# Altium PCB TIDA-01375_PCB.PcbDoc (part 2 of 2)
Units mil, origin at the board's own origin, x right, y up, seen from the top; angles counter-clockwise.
Board outline 3937.01 x 3149.61 mil, 2 copper layers (Top Layer, Bottom Layer), stack 62 mil thick; 52 components, 33 nets, 136 pads, 897 vias.
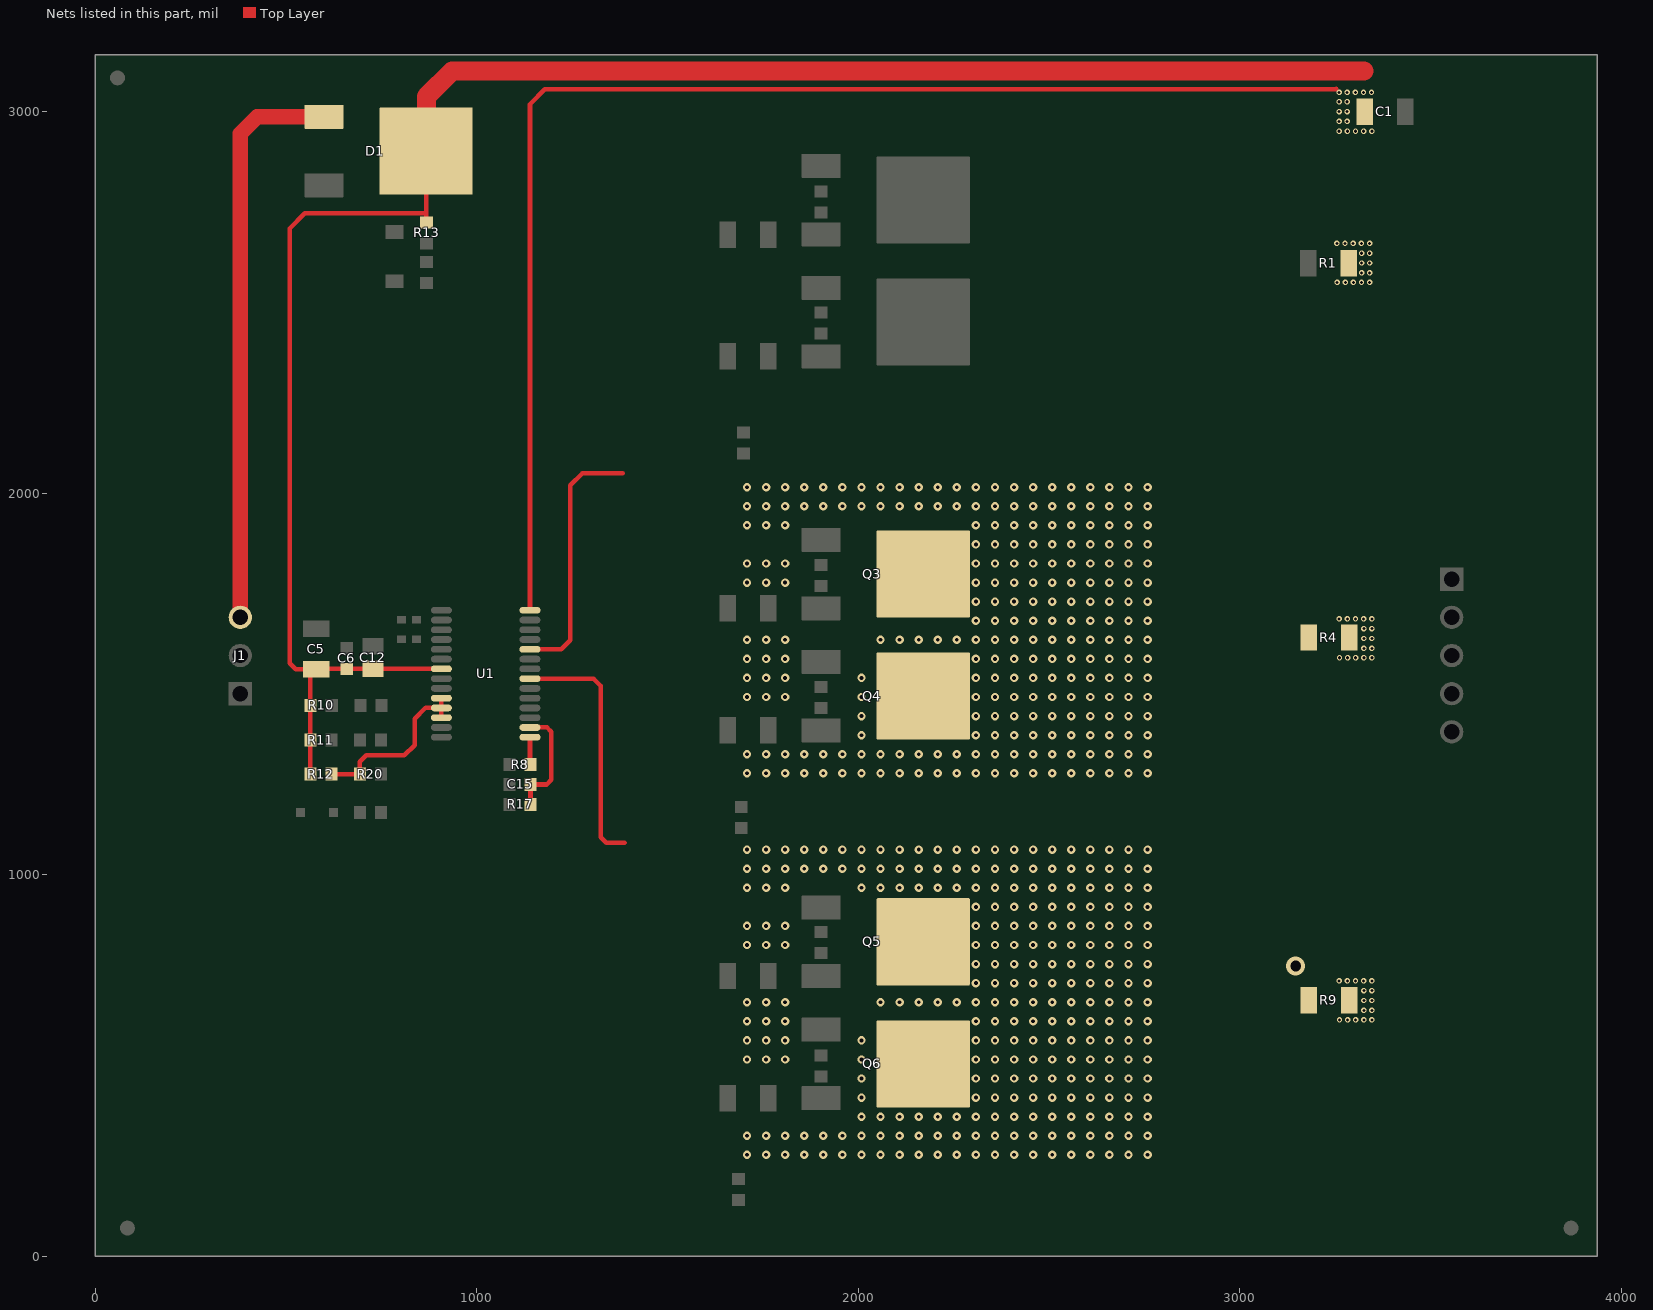
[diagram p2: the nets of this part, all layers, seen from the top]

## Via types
v1: diameter 22, hole 10, Top Layer to Bottom Layer, 824 vias
v2: diameter 14, hole 8, Top Layer to Bottom Layer, 64 vias
v3: diameter 30, hole 18, Top Layer to Bottom Layer, 8 vias
v4: diameter 50, hole 28, Top Layer to Bottom Layer, 1 vias

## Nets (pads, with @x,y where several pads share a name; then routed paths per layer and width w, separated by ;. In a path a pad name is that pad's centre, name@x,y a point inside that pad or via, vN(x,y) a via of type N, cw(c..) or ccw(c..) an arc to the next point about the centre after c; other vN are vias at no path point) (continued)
NetQ3_4: Q3.4 Q4.4 R4.1 U1.24 | length 671.6
  Top Layer w12: U1.24@1139.14,1590.98 1220.98,1590.98 1244.75,1614.75 1244.75,2020.75 1276,2052 1382,2052
  other v1: 1708,1266 1758,1266 1808,1266 1858,1266 1908,1266 1958,1266 2008,1266 2058,1266 2108,1266 2158,1266 2208,1266 2258,1266 2308,1266 2358,1266 2408,1266 2458,1266 2508,1266 2558,1266 2608,1266 2658,1266 2708,1266 2758,1266 1708,1316 1758,1316 1808,1316 1858,1316 1908,1316 1958,1316 2008,1316 2058,1316 2108,1316 2158,1316 2208,1316 2258,1316 2308,1316 2358,1316 2408,1316 2458,1316 2508,1316 2558,1316 2608,1316 2658,1316 2708,1316 2758,1316 2008,1366 2308,1366 2358,1366 2408,1366 2458,1366 2508,1366 2558,1366 2608,1366 2658,1366 2708,1366 2758,1366 2008,1416 2308,1416 2358,1416 2408,1416 2458,1416 2508,1416 2558,1416 2608,1416 2658,1416 2708,1416 2758,1416 1708,1466 1758,1466 1808,1466 2008,1466 2308,1466 2358,1466 2408,1466 2458,1466 2508,1466 2558,1466 2608,1466 2658,1466 2708,1466 2758,1466 1708,1516 1758,1516 1808,1516 2008,1516 2308,1516 2358,1516 2408,1516 2458,1516 2508,1516 2558,1516 2608,1516 2658,1516 2708,1516 2758,1516 1708,1566 1758,1566 1808,1566 2308,1566 2358,1566 2408,1566 2458,1566 2508,1566 2558,1566 2608,1566 2658,1566 2708,1566 2758,1566 1708,1616 1758,1616 1808,1616 2058,1616 2108,1616 2158,1616 2208,1616 2258,1616 2308,1616 2358,1616 2408,1616 2458,1616 2508,1616 2558,1616 2608,1616 2658,1616 2708,1616 2758,1616 2308,1666 2358,1666 2408,1666 2458,1666 2508,1666 2558,1666 2608,1666 2658,1666 2708,1666 2758,1666 2308,1716 2358,1716 2408,1716 2458,1716 2508,1716 2558,1716 2608,1716 2658,1716 2708,1716 2758,1716 1708,1766 1758,1766 1808,1766 2308,1766 2358,1766 2408,1766 2458,1766 2508,1766 2558,1766 2608,1766 2658,1766 2708,1766 2758,1766 1708,1816 1758,1816 1808,1816 2308,1816 2358,1816 2408,1816 2458,1816 2508,1816 2558,1816 2608,1816 2658,1816 2708,1816 2758,1816 2308,1866 2358,1866 2408,1866 2458,1866 2508,1866 2558,1866 2608,1866 2658,1866 2708,1866 2758,1866 1708,1916 1758,1916 1808,1916 2308,1916 2358,1916 2408,1916 2458,1916 2508,1916 2558,1916 2608,1916 2658,1916 2708,1916 2758,1916 1708,1966 1758,1966 1808,1966 1858,1966 1908,1966 1958,1966 2008,1966 2058,1966 2108,1966 2158,1966 2208,1966 2258,1966 2308,1966 2358,1966 2408,1966 2458,1966 2508,1966 2558,1966 2608,1966 2658,1966 2708,1966 2758,1966 1708,2016 1758,2016 1808,2016 1858,2016 1908,2016 1958,2016 2008,2016 2058,2016 2108,2016 2158,2016 2208,2016 2258,2016 2308,2016 2358,2016 2408,2016 2458,2016 2508,2016 2558,2016 2608,2016 2658,2016 2708,2016 2758,2016
NetQ5_4: Q5.4 Q6.4 R9.1 U1.21 | length 658.6
  Top Layer w12: U1.21@1139.14,1514.2 1305.8,1514.2 1325,1495 1325,1098 1339,1084 1387,1084
  other v1: 1708,266 1758,266 1808,266 1858,266 1908,266 1958,266 2008,266 2058,266 2108,266 2158,266 2208,266 2258,266 2308,266 2358,266 2408,266 2458,266 2508,266 2558,266 2608,266 2658,266 2708,266 2758,266 1708,316 1758,316 1808,316 1858,316 1908,316 1958,316 2008,316 2058,316 2108,316 2158,316 2208,316 2258,316 2308,316 2358,316 2408,316 2458,316 2508,316 2558,316 2608,316 2658,316 2708,316 2758,316 2008,366 2058,366 2108,366 2158,366 2208,366 2258,366 2308,366 2358,366 2408,366 2458,366 2508,366 2558,366 2608,366 2658,366 2708,366 2758,366 2008,416 2308,416 2358,416 2408,416 2458,416 2508,416 2558,416 2608,416 2658,416 2708,416 2758,416 2008,466 2308,466 2358,466 2408,466 2458,466 2508,466 2558,466 2608,466 2658,466 2708,466 2758,466 1708,516 1758,516 1808,516 2008,516 2308,516 2358,516 2408,516 2458,516 2508,516 2558,516 2608,516 2658,516 2708,516 2758,516 1708,566 1758,566 1808,566 2008,566 2308,566 2358,566 2408,566 2458,566 2508,566 2558,566 2608,566 2658,566 2708,566 2758,566 1708,616 1758,616 1808,616 2308,616 2358,616 2408,616 2458,616 2508,616 2558,616 2608,616 2658,616 2708,616 2758,616 1708,666 1758,666 1808,666 2058,666 2108,666 2158,666 2208,666 2258,666 2308,666 2358,666 2408,666 2458,666 2508,666 2558,666 2608,666 2658,666 2708,666 2758,666 2308,716 2358,716 2408,716 2458,716 2508,716 2558,716 2608,716 2658,716 2708,716 2758,716 2308,766 2358,766 2408,766 2458,766 2508,766 2558,766 2608,766 2658,766 2708,766 2758,766 1708,816 1758,816 1808,816 2308,816 2358,816 2408,816 2458,816 2508,816 2558,816 2608,816 2658,816 2708,816 2758,816 1708,866 1758,866 1808,866 2308,866 2358,866 2408,866 2458,866 2508,866 2558,866 2608,866 2658,866 2708,866 2758,866 2308,916 2358,916 2408,916 2458,916 2508,916 2558,916 2608,916 2658,916 2708,916 2758,916 1708,966 1758,966 1808,966 2008,966 2058,966 2108,966 2158,966 2208,966 2258,966 2308,966 2358,966 2408,966 2458,966 2508,966 2558,966 2608,966 2658,966 2708,966 2758,966 1708,1016 1758,1016 1808,1016 1858,1016 1908,1016 1958,1016 2008,1016 2058,1016 2108,1016 2158,1016 2208,1016 2258,1016 2308,1016 2358,1016 2408,1016 2458,1016 2508,1016 2558,1016 2608,1016 2658,1016 2708,1016 2758,1016 1708,1066 1758,1066 1808,1066 1858,1066 1908,1066 1958,1066 2008,1066 2058,1066 2108,1066 2158,1066 2208,1066 2258,1066 2308,1066 2358,1066 2408,1066 2458,1066 2508,1066 2558,1066 2608,1066 2658,1066 2708,1066 2758,1066
  other v4: 3146,761
NetR8_2: R8.2 U1.15 | length 72.2
  Top Layer w12: U1.15@1139.14,1360.66 1139.14,1290.42 R8.2@1140.56,1289
PL: D1.1 J1.3 | length 1505.5
  Top Layer w40: J1.3@380,1674.8 380,2943 423.76,2986.76 D1.1@599.14,2986.76
PWMCHG: C15.1 R17.2 U1.16 | length 298.3
  Top Layer w12: U1.16@1139.14,1386.25 1183.75,1386.25 1195,1375 1195,1249 1182.71,1236.71 C15.1@1140.56,1236.71 R17.2@1140.56,1184.43
PWMIN: R12.1 R20.2 U1.10 U1.11 U1.12 | length 470.7
  Top Layer w12: R12.1@618.56,1264 R20.2@693.44,1264 693.44,1296.44 710,1313 810,1313 837,1340 837,1409 865.43,1437.43 U1.11@906.86,1437.43 ; U1.12@906.86,1411.84 U1.11@906.86,1437.43 ; U1.10@906.86,1463.02 U1.11@906.86,1437.43
VIN: C1.1 C5.1 C6.1 C12.2 D1.4 R1.2 R4.2 R9.2 R10.2 R11.2 R12.2 R13.2 U1.7 U1.28 | length 8361.2
  Top Layer w12: R12.2@563.44,1264 R11.2@563.44,1353 563.44,1523.1 C5.1@579,1538.66 ; D1.4@866.86,2897 866.86,2737 ; R13.2@868,2710.09 866.86,2711.23 866.86,2737 ; U1.7@906.86,1539.8 727.34,1539.8 C12.2@727.18,1539.64 579.98,1539.64 C5.1@579,1538.66 ; U1.28@1139.14,1693.34 1139.14,3020.14 1178,3059 3251,3059 3252,3060 ; C5.1@579,1538.66 525.34,1538.66 509,1555 509,2694 549,2734 863.86,2734 866.86,2737
  Top Layer w50: D1.4@868,3008 868,3040 935,3107 3325,3107
  other v2: 3261,620 3282.25,620 3303.5,620 3324.75,620 3346,620 3325,644.75 3346,644.75 3325,670.5 3346,670.5 3325,696.25 3346,696.25 3260,722 3281.5,722 3303,722 3324.5,722 3346,722 3261,1569 3282.25,1569 3303.5,1569 3324.75,1569 3346,1569 3325,1593.75 3346,1593.75 3325,1619.5 3346,1619.5 3325,1645.25 3346,1645.25 3260,1671 3281.5,1671 3303,1671 3324.5,1671 3346,1671 3255,2553 3276.25,2553 3297.5,2553 3318.75,2553 3340,2553 3319,2577.75 3340,2577.75 3319,2603.5 3340,2603.5 3319,2629.25 3340,2629.25 3254,2655 3275.5,2655 3297,2655 3318.5,2655 3340,2655 3260,2949 3281.5,2949 3303,2949 3324.5,2949 3346,2949 3260,2974.75 3281,2974.75 3260,3000.5 3281,3000.5 3260,3026.25 3281,3026.25 3260,3051 3281.25,3051 3302.5,3051 3323.75,3051 3345,3051
pads on no net: FID1.1 FID2.1 FID3.1 U1.18

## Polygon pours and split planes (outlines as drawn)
GND on Top Layer "Top Layer-No Net1" (solid, remove dead copper, pour order 12): 0,0 3937.01,0 3937.01,3149.61 0,3149.61
NetQ1_4 on Top Layer "Top Layer-No Net" (solid, remove dead copper, pour order 4): 1368.8,3037.55 1369.8,3037.55 3203.8,3037.55 3203.8,2186.55 3203.8,2185.55 3202.8,2185.55 1368.8,2186.55
NetQ3_4 on Top Layer "Top Layer-No Net" (solid, remove dead copper, pour order 2): 1368.8,2059 1369.8,2059 3203.8,2059 3203.8,1208 3203.8,1207 3202.8,1207 1368.8,1207
NetQ5_4 on Top Layer "Top Layer-No Net" (solid, remove dead copper, pour order 0): 1368.8,1092.45 1369.8,1092.45 3200,1092.45 3200,240.45 1368.8,241.45
GND on Bottom Layer "Top Layer-No Net2" (solid, remove dead copper, pour order 13): 0,0 3937.01,0 3937.01,3149.61 0,3149.61
NetQ5_4 on Bottom Layer "Top Layer-No Net" (solid, remove dead copper, pour order 10): 1368.8,1092.45 1369.8,1092.45 3200,1092.45 3200,240.45 1368.8,241.45
NetQ3_4 on Bottom Layer "Top Layer-No Net" (solid, remove dead copper, pour order 8): 1368.8,2059 1369.8,2059 3203.8,2059 3203.8,1208 3203.8,1207 3202.8,1207 1368.8,1207
NetQ1_4 on Bottom Layer "Top Layer-No Net" (solid, remove dead copper, pour order 6): 1368.8,3037.55 1369.8,3037.55 3203.8,3037.55 3203.8,2186.55 3203.8,2185.55 3202.8,2185.55 1368.8,2186.55

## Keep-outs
Keep-Out Layer:
  the board outline again, w10
  text ".Layer_Name" at 577,-858.49 h60

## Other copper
Top Layer:
  rectangle net VIN: 3246,599 3358,749
  rectangle net VIN: 3246,1548 3358,1698
  rectangle net VIN: 3244,2535 3358,3132
  text ".Layer_Name" at 577,-858.49 h60
Bottom Layer:
  rectangle net VIN: 3246,599 3358,3131
  text ".Layer_Name" at 577,-858.49 h60

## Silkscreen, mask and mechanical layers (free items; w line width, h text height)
Top Overlay:
  text ".PRJ_Number" at 369,110 h60
  text ".PCB_Rev" at 969,110 h60
  text ".Layer_Name" at 577,-858.49 h60
Bottom Overlay:
  text ".Layer_Name" at 577,-858.49 h60
Top Paste:
  text ".Layer_Name" at 577,-858.49 h60
Bottom Paste:
  text ".Layer_Name" at 577,-858.49 h60
Top Solder:
  text ".Layer_Name" at 577,-858.49 h60
  text ".Layer_Name" at 577,-858.49 h60
Bottom Solder:
  text ".Layer_Name" at 577,-858.49 h60
Drill Guide:
  text ".Layer_Name" at 577,-858.49 h60
M1 Board Outline:
  the board outline again, w10
  text ".Layer_Name" at 577,-858.49 h60
M2 Board Dimensions:
  rectangle: 0,-275 125,-150
  rectangle: 125,-400 500,-275
  lines w7: 0,-275 1000,-275 ; 125,-400 125,-150 ; 250,-400 250,-150 ; 500,-400 500,-150 ; 750,-400 750,-150 ; 0,-400 1000,-400 1000,-150 0,-150 0,-400
  text ".Layer_Name" at 577,-858.49 h60
M3 3D STEP Top:
  text ".Layer_Name" at 577,-858.49 h60
M4 3D STEP Bottom:
  text ".Layer_Name" at 577,-858.49 h60
M5 Assembly Top:
  lines w10: -292,-930.17 6308,-930.17 ; -292,-726.83 6310,-726.83 ; -292,-523.5 -292,-1133.5 3713,-1133.5 6310,-1133.5 6310,-523.5 -291.5,-523.5 -291.5,-1133.5 1284,-1133.5 ; 2173,-1133.5 2173,-523.5 ; 3440,-726.83 3440,-523.5 ; 4280,-726.83 4280,-523.5 ; 4902,-1140 4902,-937.17
  text "COMPONENTS MARKED 'DNP' SHOULD NOT BE POPULATED." at 1153.5,-318.5 h60
  text "ASSEMBLY VARIANT:" at 1153,-434 h60
  text ".VariantName" at 2189,-434 h60
  text "PCB VIEWED FROM TOP SIDE" at -228.5,-655.67 h60
  text "BOARD #:" at 2248,-655.67 h60
  text ".PRJ_Number" at 2793.5,-655.67 h60
  text "REV:" at 3638,-655.67 h60
  text ".PCB_Rev" at 3929.5,-655.67 h60
  text "SVN REV:" at 4476,-655.67 h60
  text ".VersionControl_RevNumber" at 4982,-655.67 h60
  text "TID #:" at 2248,-859 h60
  text ".TID" at 2793.5,-859 h60
  text "PLOT NAME =" at -228.5,-1064.34 h60
  text ".plot_File_Name" at 577,-1064.34 h60
  text "GENERATED    :" at 2250,-1064.34 h60
  text ".Print_Date" at 3119.5,-1064.34 h60
  text ".Print_Time" at 3848.5,-1064.34 h60
  text "TEXAS INSTRUMENTS" at 5113,-1064.34 h60
M6 Assembly Bottom:
  lines w10: -292.5,-727.33 6309.5,-727.33 ; -290.5,-930.67 6309.5,-930.67 ; 1115.5,-1140.5 1115.5,-937.67 ; 1737.5,-727.33 1737.5,-524 ; 2577.5,-727.33 2577.5,-524 ; 3844.5,-1134 3844.5,-524 ; 4733.5,-1134 6309,-1134 6309,-524 -292.5,-524 -292.5,-1134 2304.5,-1134 6309.5,-1134 6309.5,-524
  text "COMPONENTS MARKED 'DNP' SHOULD NOT BE POPULATED." at 6102,-318 h60
  text ".VariantName" at 5058,-434 h60
  text "ASSEMBLY VARIANT:" at 6097,-434 h60
  text ".VersionControl_RevNumber" at 1035.5,-656.17 h60
  text "SVN REV:" at 1541.5,-656.17 h60
  text ".PCB_Rev" at 2088,-656.17 h60
  text "REV:" at 2379.5,-656.17 h60
  text ".PRJ_Number" at 3224,-656.17 h60
  text "BOARD #:" at 3769.5,-656.17 h60
  text "PCB VIEWED FROM BOTTOM SIDE" at 6246,-656.17 h60
  text ".TID" at 3224,-859.5 h60
  text "TID #:" at 3769.5,-859.5 h60
  text "TEXAS INSTRUMENTS" at 904.5,-1064.84 h60
  text ".Print_Time" at 2169,-1064.84 h60
  text ".Print_Date" at 2898,-1064.84 h60
  text "GENERATED    :" at 3767.5,-1064.84 h60
  text ".plot_File_Name" at 5440.5,-1064.84 h60
  text "PLOT NAME =" at 6246,-1064.84 h60
M9 Title Sheet:
  drawing of 57 lines, arcs and shapes, not listed
  text "1" at 739.84,8036.5 h70
  text "2" at 3235.5,8036.5 h70
  text "3" at 5724.84,8036.5 h70
  text "4" at 8231.51,8036.5 h70
  text "5" at 10730.5,8036.5 h70
  text "6" at 13235.5,8036.5 h70
  text "A" at -416.5,6893.5 h70
  text "A" at 14383.5,6893.5 h70
  text "B" at -416.5,4513.5 h70
  text "B" at 14383.5,4513.5 h70
  text "C" at -416.5,2138.5 h70
  text "C" at 14383.5,2138.5 h70
  text "PROJECT TITLE:" at 11343.5,277.5 h45
  text ".PRJ_Title" at 11393.5,144.17 h70
  text "DESIGNED FOR:" at 11343.5,-23.5 h45
  text ".PRJ_Customer" at 11393.5,-163.5 h70
  text "D" at -416.5,-231.5 h70
  text "D" at 14383.5,-231.5 h70
  text "FILE NAME:" at 11343.5,-323.5 h45
  text ".PCB_File_Name_No_Path" at 11393.5,-443.5 h70
  text "Texas Instruments (TI) and/or its licensors do not warrant the accuracy or completeness of this specification" at 6374,-605.34 h45
  text "ENGINEER:" at 11343.5,-613.5 h45
  text "LAYOUT BY:" at 12848.5,-613.5 h45
  text "or any information contained therein. TI and/or its licensors do not warrant that this design will meet" at 6329.01,-718 h45
  text ".PRJ_Engineer" at 11393.5,-768.49 h70
  text ".PCB_Layout" at 12899,-768.49 h70
  text "the specifications, will be suitable for your application or fit for any particular purpose, or will operate in" at 6329.01,-830.67 h45
  text ".Layer_Name" at 577,-858.49 h60
  text "ALTIUM DESIGNER VERSION:" at 12848.5,-923.5 h45
  text "an implementation. TI and/or its licensors do not warrant that the design is production worthy. You should" at 6329.01,-943.33 h45
  text "completely validate and test your design implementation to confirm the system functionality for your application." at 6374,-1056 h45
  text ".print_Scale" at 11393.5,-1056.83 h70
  text ".Application_BuildNumber" at 12899,-1056.83 h70
  text "1" at 739.84,-1263.5 h70
  text "2" at 3235.5,-1263.5 h70
  text "3" at 5724.84,-1263.5 h70
  text "4" at 8231.51,-1263.5 h70
  text "5" at 10730.5,-1263.5 h70
  text "6" at 13235.5,-1263.5 h70
M10 Fab Notes:
  drawing of 173 lines, arcs and shapes, not listed
  text "DESIGN INFORMATION" at 12377.02,6201 h60
  text "MIN. TRACK WIDTH:" at 11732.46,6021 h60
  text "8" at 12828.7,6021 h60
  text "MIL" at 12983.46,6021 h60
  text "MIN. CLEARANCE:" at 11732.46,5889 h60
  text "0.2" at 12768.7,5889 h60
  text "mm" at 12983.46,5889 h60
  text "MIN. VIA PAD SIZE:" at 11732.46,5757 h60
  text "24" at 12798.71,5757 h60
  text "MIL" at 12983.46,5757 h60
  text "0.05mm (2MIL)" at 12427.46,5615.29 h60
  text "MINIMUM ANNULAR RING" at 11403.23,5611 h60
  text "EXTERNAL" at 13135.46,5611 h60
  text "PER" at 11603.23,5493 h60
  text "IPC-D-275 CLASS 2 LEVEL C" at 11823.23,5493 h60
  text "MIL, HOLES" at 13311.46,5380.71 h60
  text "+/-" at 12919,5380 h60
  text "+/-" at 13773,5380 h60
  text "REGISTRATION TOLERANCES:" at 11403.23,5375 h60
  text "METAL" at 12603,5375 h60
  text "5" at 13179.2,5375 h60
  text "3" at 14012.2,5375 h60
  text "MIL" at 14128.46,5375 h60
  text "+/-" at 13773,5262 h60
  text "HOLE SIZE TOLERANCE (UNLESS OTHERWISE SPECIFIED):" at 11403.23,5257 h60
  text "3" at 14012.2,5257 h60
  text "MIL" at 14128.46,5257 h60
  text "MATERIAL:" at 11328.46,5047.54 h60
  text "FR-4 High Tg" at 12314.9,4907.21 h60
  text "FR-408" at 11749.46,4898.64 h60
  text "OTHER" at 13237.46,4898.64 h60
  text "X" at 12160,4895 h60
  text "62 MIL (1.6mm) +/-10%" at 12069.56,4735.92 h60
  text "THICKNESS:" at 11403.23,4731.64 h60
  text "X" at 11941.4,4731.64 h60
  text "OTHER" at 13354.46,4731.64 h60
  text "TOLERANCE:" at 11403.23,4573.64 h60
  text "X" at 12242.53,4573.64 h60
  text "ANSI IPC-6012 TYPE 3 CLASS 2" at 12429.48,4573.64 h60
  text "OTHER +/-" at 12429.46,4417.64 h60
  text "BOW & TWIST:" at 11403.23,4260.64 h60
  text "X" at 12242.53,4260.64 h60
  text "ANSI IPC-6012 TYPE 3 CLASS 2" at 12429.48,4260.64 h60
  text "OTHER +/-" at 12429.46,4102.13 h60
  text "DRILLING:" at 11328.46,3963.64 h60
  text "REFERENCE:" at 11403.23,3846.64 h60
  text "X" at 12051.46,3846.64 h60
  text "AS SHOWN" at 12238.46,3846.64 h60
  text "X" at 12952.46,3846.64 h60
  text "NC_DRILL FILES" at 13089.46,3846.64 h60
  text "PTH COPPER THICKNESS:" at 11403.23,3688.64 h60
  text "X" at 12533.46,3688.64 h60
  text "20-30 um" at 12670.46,3688.64 h60
  text "OTHER" at 13387.46,3688.64 h60
  text "BOARD FINISH:" at 11328.46,3529.64 h60
  text "SILKSCREEN:" at 11483.68,3411.64 h60
  text "X" at 12432.46,3411.64 h60
  text "TOP" at 12558.46,3411.64 h60
  text "X" at 12942.46,3411.64 h60
  text "BOTTOM" at 13069.46,3411.64 h60
  text "SILKSCREEN COLOR:" at 11483.68,3244.64 h60
  text "X" at 12431.42,3244.64 h60
  text "WHITE" at 12558.46,3244.64 h60
  text "OTHER" at 13069.46,3244.64 h60
  text "X" at 12562.42,3085.44 h60
  text "GREEN" at 12689.46,3085.44 h60
  text "OTHER" at 13307.46,3085.44 h60
  text "SOLDER RESIST COLOR:" at 11483.68,3074.64 h60
  text "X" at 12562.42,2915.44 h60
  text "MATTE" at 12689.46,2915.44 h60
  text "SEMI-GLOSS" at 13307,2914.8 h60
  text "IMMERSION GOLD (ENIG)" at 12389.46,2726.92 h60
  text "ENEPIG" at 13727,2723.64 h60
  text "SURFACE FINISH:" at 11328.46,2722.64 h60
  text "X" at 12202.51,2722.64 h60
  text "IMM. TIN/SILVER OR EQUIV" at 11658,2565.64 h60
  text "OTHER" at 13089.46,2565.64 h60
  text "ARRAY/PANEL:" at 11328.46,2386.64 h60
  text "CUT AND TRIM PER M1 BOARD OUTLINE" at 12389.46,2382.35 h60
  text "N.C. ROUTE" at 12389.46,2230.64 h60
  text "X" at 13068.46,2230.64 h60
  text "V. SCORE" at 13255.46,2230.64 h60
  text "CERTIFICATION:" at 11328.46,2093.64 h60
  text "MATERIALS AND WORKMANSHIP FOR ALL PCBS" at 12053.46,2093.64 h60
  text "TO MEET OR EXCEED THE REQUIREMENTS OF:" at 12053.46,1995.64 h60
  text "X" at 11679.96,1859.13 h60
  text "ANSI IPC-A-600F CLASS ->" at 11818.96,1859.13 h60
  text "X" at 13458.02,1859.13 h60
  text "2" at 13576.96,1859.14 h60
  text "1" at 13261.96,1857.64 h60
  text "3" at 13930.96,1857.64 h60
  text "X" at 12494.02,1699.64 h60
  text "RoHS" at 12630.96,1699.64 h60
  text "OTHER" at 13275.36,1699.64 h60
  text "PER ORDER" at 13672.42,1699.64 h60
  text "ALL BOARDS MUST MEET OR EXCEED UL94-V0 REQUIREMENTS." at 11356,1534 h60
  text "PCB MUST BEAR THE UL94V-0 UL REGISTERED MATERIAL ID NUMBER" at 11356,1414 h60
  text "ADDITIONAL REQUIREMENTS:" at 11328.46,1240.64 h60
  text "MICROSECTION:" at 11403.23,1125.64 h60
  text "YES" at 12308.96,1125.64 h60
  text "REQUIRED" at 13170.46,969.49 h60
  text "BARE BOARD ELEC. TEST:" at 11403.23,966.64 h60
  text "NONE" at 12708.96,966.64 h60
  text "X" at 13043.46,966.64 h60
  text "PER ORDER" at 13762.46,966.64 h60
  text ".Layer_Name" at 577,-858.49 h60
M11 Gerber Information:
  lines w10: -292,-930.17 6308,-930.17 ; -292,-726.83 6310,-726.83 ; -292,-523.5 -292,-1133.5 3713,-1133.5 6310,-1133.5 6310,-523.5 -291.5,-523.5 -291.5,-1133.5 1284,-1133.5 ; 2173,-1133.5 2173,-523.5 ; 3440,-726.83 3440,-523.5 ; 4280,-726.83 4280,-523.5 ; 4902,-1140 4902,-937.17
  text "ALL ARTWORK VIEWED FROM TOP SIDE" at -228.5,-655.67 h60
  text "BOARD #:" at 2248,-655.67 h60
  text ".PRJ_Number" at 2793.5,-655.67 h60
  text "REV:" at 3638,-655.67 h60
  text ".PCB_Rev" at 3929.5,-655.67 h60
  text "SVN REV:" at 4476,-655.67 h60
  text ".VersionControl_RevNumber" at 4982,-655.67 h60
  text "LAYER NAME =" at -228.5,-858.49 h60
  text "TID #:" at 2248,-859 h60
  text ".TID" at 2793.5,-859 h60
  text "PLOT NAME =" at -228.5,-1064.34 h60
  text ".plot_File_Name" at 577,-1064.34 h60
  text "GENERATED    :" at 2250,-1064.34 h60
  text ".Print_Date" at 3119.5,-1064.34 h60
  text ".Print_Time" at 3848.5,-1064.34 h60
  text "TEXAS INSTRUMENTS" at 5113,-1064.34 h60
M12 Stackup:
  drawing of 191 lines, arcs and shapes, not listed
  text "Layer" at 9790.58,7830 h60
  text "Name" at 10200.49,7830 h60
  text "Material" at 11130.23,7830 h60
  text "Thickness" at 11990,7830 h60
  text "Constant" at 12639.84,7830 h60
  text "Board Layer Stack" at 13209.7,7830 h60
  text "1" at 9790.58,7710 h60
  text "Top Overlay" at 10200.49,7710 h60
  text "2" at 9790.58,7590 h60
  text "Top Solder" at 10200.49,7590 h60
  text "Solder Resist" at 11130.23,7590 h60
  text "0.40mil" at 11990,7590 h60
  text "3.5" at 12639.84,7590 h60
  text "3" at 9790.58,7470 h60
  text "Top Layer" at 10200.49,7470 h60
  text "Copper" at 11130.23,7470 h60
  text "1.40mil" at 11990,7470 h60
  text "4" at 9790.58,7350 h60
  text "Dielectric1" at 10200.49,7350 h60
  text "FR-4" at 11130.23,7350 h60
  text "59.20mil" at 11990,7350 h60
  text "4.8" at 12639.84,7350 h60
  text "5" at 9790.58,7230 h60
  text "Bottom Layer" at 10200.49,7230 h60
  text "Copper" at 11130.23,7230 h60
  text "1.40mil" at 11990,7230 h60
  text "6" at 9790.58,7110 h60
  text "Bottom Solder" at 10200.49,7110 h60
  text "Solder Resist" at 11130.23,7110 h60
  text "0.40mil" at 11990,7110 h60
  text "3.5" at 12639.84,7110 h60
  text "7" at 9790.58,6990 h60
  text "Bottom Overlay" at 10200.49,6990 h60
  text ".Layer_Name" at 577,-858.49 h60
M13 Component Bodies Top:
  text ".Layer_Name" at 577,-858.49 h60
M14 Component Bodies Bottom:
  text ".Layer_Name" at 577,-858.49 h60
M15 Courtyards Top:
  text ".Layer_Name" at 577,-858.49 h60
M16 Courtyards Bottom:
  text ".Layer_Name" at 577,-858.49 h60
Drill Drawing:
  circle w10: c5563.72,2893.32 r27.63
  lines w10: 5536.09,2796.63 5591.34,2796.63 5563.72,2741.38 5536.09,2796.63 ; 5536.09,3003.83 5549.9,3003.83 5563.72,2990.02 5577.53,3003.83 5591.34,3003.83 5577.53,3017.64 5591.34,3031.46 5577.53,3031.46 5563.72,3045.27 5549.9,3031.46 5536.09,3031.46 5549.9,3017.64 5536.09,3003.83 ; 5536.09,3114.34 5591.34,3114.34 5591.34,3169.59 5536.09,3169.59 5536.09,3114.34 ; 5536.09,3252.47 5549.9,3252.47 5549.9,3238.66 5577.53,3238.66 5577.53,3252.47 5591.34,3252.47 5591.34,3280.1 5577.53,3280.1 5577.53,3293.91 5549.9,3293.91 5549.9,3280.1 5536.09,3280.1 5536.09,3252.47
  lines w12: 5486,2704.08 7464.02,2704.08 ; 5486,3325.68 7464.02,3325.68 ; 5823.86,2579.76 5823.86,3450 ; 6155.86,2579.76 6155.86,3450 ; 6792.43,2579.76 6792.43,3450 ; 7051.57,2579.76 7051.57,3450 ; 5486,2579.76 7464.02,2579.76 7464.02,3450 5486,3450 5486,2579.76
  text "Symbol" at 5560.59,3362.98 h72
  text "Quantity" at 5861.16,3362.98 h72
  text "Finished Hole Size" at 6193.16,3362.98 h72
  text "Plated" at 6829.72,3362.98 h72
  text "Hole Type" at 7088.86,3362.98 h72
  text "64" at 5861.16,3238.66 h60
  text "8.00mil (0.203mm)" at 6193.16,3238.66 h60
  text "PTH" at 6829.72,3238.66 h60
  text "Round" at 7088.86,3238.66 h60
  text "824" at 5861.16,3114.34 h60
  text "10.00mil (0.254mm)" at 6193.16,3114.34 h60
  text "PTH" at 6829.72,3114.34 h60
  text "Round" at 7088.86,3114.34 h60
  text "8" at 5861.16,2990.02 h60
  text "18.00mil (0.457mm)" at 6193.16,2990.02 h60
  text "PTH" at 6829.72,2990.02 h60
  text "Round" at 7088.86,2990.02 h60
  text "1" at 5861.16,2865.7 h60
  text "28.00mil (0.711mm)" at 6193.16,2865.7 h60
  text "PTH" at 6829.72,2865.7 h60
  text "Round" at 7088.86,2865.7 h60
  text "8" at 5861.16,2741.38 h60
  text "40.16mil (1.020mm)" at 6193.16,2741.38 h60
  text "PTH" at 6829.72,2741.38 h60
  text "Round" at 7088.86,2741.38 h60
  text "905 Total" at 5861.16,2617.06 h60
  text ".Layer_Name" at 577,-858.49 h60

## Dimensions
0,-400 to 1000,-400 on M2 Board Dimensions
0,0 to 0,3149.61 on M2 Board Dimensions
0,0 to 3937.01,0 on M2 Board Dimensions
